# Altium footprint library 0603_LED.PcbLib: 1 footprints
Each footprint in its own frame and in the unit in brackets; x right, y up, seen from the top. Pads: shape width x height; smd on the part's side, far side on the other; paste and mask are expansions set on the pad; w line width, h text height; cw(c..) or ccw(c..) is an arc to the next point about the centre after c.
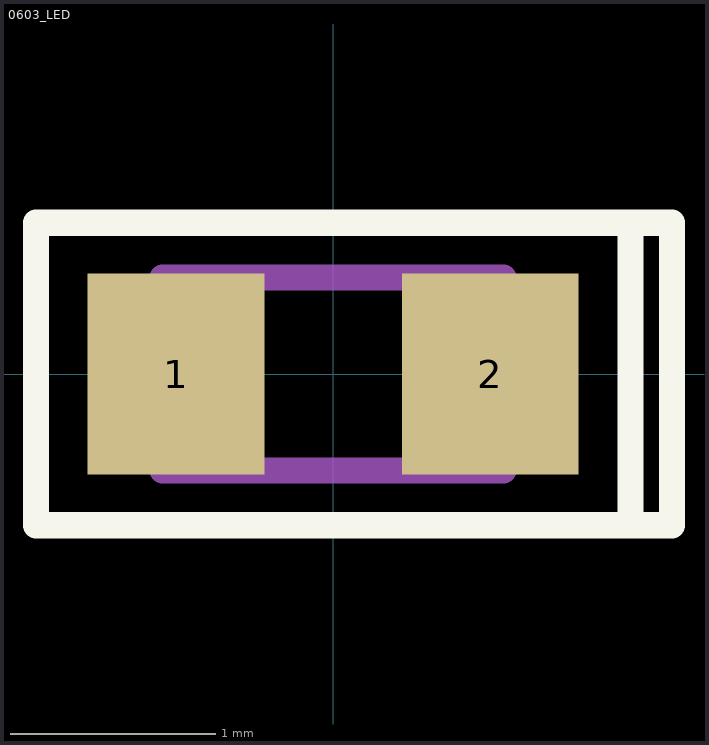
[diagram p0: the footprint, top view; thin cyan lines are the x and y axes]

## 0603_LED [mm]
pads (2):
  rect 0.86x0.98 smd mask+0.05: 1(-0.765,0) 2(0.765,0)
Top Overlay:
  lines w0.127: 1.448,-0.737 1.651,-0.737 1.651,0.737 1.448,0.737 ; 1.448,-0.737 1.448,0.737 ; 1.448,-0.737 -1.448,-0.737 -1.448,0.737 1.448,0.737
Mechanical 13:
  lines w0.127: -0.83,-0.47 -0.83,0.47 0.83,0.47 0.83,-0.47 -0.83,-0.47
Mechanical 15:
  lines w0.05: -1.444,-0.74 -1.444,0.74 1.444,0.74 1.444,-0.74 -1.444,-0.74
3D body "step_temp.STEP": height 0.55, standoff 0, extent -0.775,-0.425 0.775,0.425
